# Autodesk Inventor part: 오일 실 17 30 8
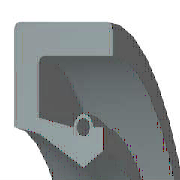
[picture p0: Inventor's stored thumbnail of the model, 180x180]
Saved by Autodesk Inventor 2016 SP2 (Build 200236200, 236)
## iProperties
Created: 2012-02
Part Number: 오일 실 17 30 8
Material: 고무
Description: 오일-실
Document SubType Name: Modeling
Standard: KS B 2804
Designer: mduedu
Standards Organization: KS
Language: ko-KR
Size Designation: S - 17 30 8
Categories: <MemberInstance><Categories><Category DisplayName="샤프트 부품" InternalName="7f7aeb1f-a693-4053-b835-cee3144e0d98" Mnemonic="SHFT"><Category DisplayName="실링" Intern
Density: 0.93 g/cm^3
Appearance: 고무 - 검은색 - 버전 1.1
IsCustomPart: 1
Author: mduedu
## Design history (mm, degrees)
revolve "본체" stored, may be unused: angle "d17" = 90 deg
revolve "스프링1" stored, may be unused: angle "d18" = 90 deg
body "Solid1"
sketch "스케치1"
  geometry: L1 (0, 15)-(8, 15); L2 (8, 15)-(8, 13.75); L3 (8, 13.75)-(1.75, 13.75); L4 (0, 15)-(0, 10.6); L5 (0, 10.6)-(1.75, 10.25); L6 (1.75, 10.25)-(4.9, 8.5); L7 (4.9, 8.5)-(0, 8.5); L8 (6.3, 9.375)-(6.3, 10.6); L9 (0, 0)-(9.586, 0) reference; L10 (4.9, 8.5)-(6.3, 9.375); L11 (0, 18)-(0, -3) reference; L12 (-1.917, 0)-(11.503, 0) reference; L13 (4.2, 10.6)-(1.75, 11.09); L14 (1.75, 11.09)-(1.75, 13.75); L15 (6.3, 10.6)-(5.6, 10.6); C1 r 0.455 at (4.9, 10.6); A1 r 0.7 centre (4.9, 10.6) between (5.6, 10.6) and (4.2, 10.6)
  constraints: 26 end point, 5 horizontal alignment, 4 perpendicular, 2 centre point, 2 collinear, 2 horizontal, 2 parallel, 2 point on circle, 2 point on line, 2 vertical alignment, 1 coincident
  dimensions: "d0" = 30 diameter of L1 L9 (= SD2); "d1" = 18.75 diameter of L8.start L9 (= ABDM); "d2" = 1.25 distance of L1.end L2.end (computed from SD); "d3" = 0.91 diameter of C1 (= SPDI); "d4" = 1.4 diameter of A1 (= SPDA); "d5" = 17 diameter of L6.end L9 (= NND); "d6" = 20.5 diameter of L5.end L9 (= TKDM); "d7" = 21.2 diameter of L4.end L9 (= HLDM); "d8" = 4.9 distance from line of C1.centre L4 (= SPDST); "d9" = 6.3 distance between parallel lines of L8 L4 (= SDI); "d10" = 8 distance between parallel lines of L2 L4 (= SWDT); "d12" = 1.75 distance between parallel lines of L14 L4 (= SD)
fillet "모깎기1" dims "d11" = 0.3 (= RR)
other parameters: "SD2" = 30 [user parameter; used in 1 equation term], "SWDT" = 8 [user parameter; used in 1 equation term], "RR" = 0.3 [user parameter; used in 1 equation term], "SD" = 1.75 [user parameter; used in 2 equation terms], "NND" = 17 [user parameter; used in 1 equation term], "SPDA" = 1.4 [user parameter; used in 1 equation term], "SPDI" = 0.91 [user parameter; used in 1 equation term], "TKDM" = 20.5 [user parameter; used in 1 equation term], "HLDM" = 21.2 [user parameter; used in 1 equation term], "ABDM" = 18.75 [user parameter; used in 1 equation term], "SDI" = 6.3 [user parameter; used in 1 equation term], "SPDST" = 4.9 [user parameter; used in 1 equation term], "d13" = 0, "d14" = 0, "d15" = 0, "LAB" = 0.35 [user parameter]
